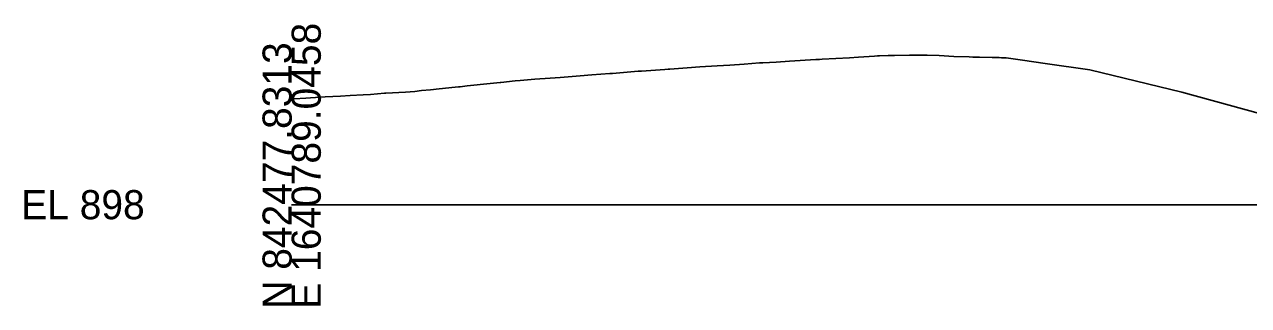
# Model space of a CAD drawing. Extents: x -26 to 1640245, y -10 to 842531.
# Drawn here: x -25.7 to 92, y 1990.3 to 2017.3 of the extents above; entities that cross this region are included whole.
import ezdxf

# ---------------------------------------------------------------- set-up
doc = ezdxf.new("R2010")
doc.units = 0
for name, color, linetype in [('Default', 7, 'Continuous'), ('Exist Cross Section Cell', 7, 'Continuous'), ('Exist XS Ground Line', 7, 'Continuous')]:
    doc.layers.add(name, color=color, linetype=linetype)

msp = doc.modelspace()

# ---------------------------------------------------------------- linework, layer by layer
at = {"layer": 'Exist Cross Section Cell'}
msp.add_line((0, 2000), (150, 2000), dxfattribs=at)
at = {"layer": 'Exist XS Ground Line'}
for p, q in [((50.76, 2013.96), (51.02, 2013.98)), ((51.02, 2013.98), (53.64, 2014.13)), ((53.64, 2014.13), (54.52, 2014.18)), ((54.52, 2014.18), (56.06, 2014.28)), ((56.06, 2014.28), (56.35, 2014.3)), ((56.35, 2014.3), (56.52, 2014.31)), ((56.52, 2014.31), (57.36, 2014.33)), ((57.36, 2014.33), (57.39, 2014.33)), ((57.39, 2014.33), (57.97, 2014.35)), ((57.97, 2014.35), (59.4, 2014.38)), ((59.4, 2014.38), (60.02, 2014.38)), ((60.02, 2014.38), (61.1, 2014.37)), ((61.1, 2014.37), (62.28, 2014.34)), ((62.28, 2014.34), (63.68, 2014.23)), ((63.68, 2014.23), (65.15, 2014.2)), ((65.15, 2014.2), (65.51, 2014.19)), ((65.51, 2014.19), (66.14, 2014.18)), ((66.14, 2014.18), (67.35, 2014.15)), ((67.35, 2014.15), (68.03, 2014.14)), ((68.03, 2014.14), (68.25, 2014.13)), ((68.25, 2014.13), (68.72, 2014.12)), ((68.72, 2014.12), (70.29, 2013.89)), ((30.85, 2012.62), (33.31, 2012.82)), ((33.31, 2012.82), (33.48, 2012.83)), ((33.48, 2012.83), (33.64, 2012.84)), ((33.64, 2012.84), (35.89, 2013)), ((35.89, 2013), (36.19, 2013.02)), ((36.19, 2013.02), (36.37, 2013.03)), ((36.37, 2013.03), (38.03, 2013.16)), ((38.03, 2013.16), (39.25, 2013.25)), ((39.25, 2013.25), (40.93, 2013.35)), ((40.93, 2013.35), (42.12, 2013.42)), ((42.12, 2013.42), (43.52, 2013.52)), ((43.52, 2013.52), (45, 2013.62)), ((45, 2013.62), (45.18, 2013.63)), ((45.18, 2013.63), (45.32, 2013.64)), ((45.32, 2013.64), (46.59, 2013.71)), ((46.59, 2013.71), (47.88, 2013.79)), ((47.88, 2013.79), (50.42, 2013.94)), ((50.42, 2013.94), (50.76, 2013.96)), ((70.29, 2013.89), (72.46, 2013.58)), ((72.46, 2013.58), (76.77, 2012.97)), ((76.77, 2012.97), (85.59, 2010.82)), ((16.87, 2011.41), (19.09, 2011.64)), ((19.09, 2011.64), (20.05, 2011.75)), ((20.05, 2011.75), (20.07, 2011.75)), ((20.07, 2011.75), (20.07, 2011.75)), ((20.07, 2011.75), (20.11, 2011.75)), ((20.11, 2011.75), (21.5, 2011.9)), ((21.5, 2011.9), (21.97, 2011.94)), ((21.97, 2011.94), (23.37, 2012.05)), ((23.37, 2012.05), (24.85, 2012.16)), ((24.85, 2012.16), (25.81, 2012.24)), ((25.81, 2012.24), (27.73, 2012.4)), ((27.73, 2012.4), (28.86, 2012.47)), ((28.86, 2012.47), (30.61, 2012.6)), ((30.61, 2012.6), (30.85, 2012.62)), ((4.7, 2010.44), (5.64, 2010.49)), ((5.64, 2010.49), (6.87, 2010.56)), ((6.87, 2010.56), (7.58, 2010.6)), ((7.58, 2010.6), (8.92, 2010.71)), ((8.92, 2010.71), (9.07, 2010.73)), ((9.07, 2010.73), (10.96, 2010.83)), ((10.96, 2010.83), (11.86, 2010.88)), ((11.86, 2010.88), (12.49, 2010.96)), ((12.49, 2010.96), (13.34, 2011.04)), ((13.34, 2011.04), (14.2, 2011.13)), ((14.2, 2011.13), (15.72, 2011.29)), ((15.72, 2011.29), (16.04, 2011.32)), ((16.04, 2011.32), (16.21, 2011.34)), ((16.21, 2011.34), (16.87, 2011.41)), ((85.59, 2010.82), (95.57, 2008.08)), ((0, 2010.17), (0.24, 2010.19)), ((0.24, 2010.19), (1.35, 2010.24)), ((1.35, 2010.24), (1.82, 2010.27)), ((1.82, 2010.27), (3.21, 2010.36)), ((3.21, 2010.36), (4.7, 2010.44))]:
    msp.add_line(p, q, dxfattribs=at)

# ---------------------------------------------------------------- texts
at = {"layer": 'Default'}
msp.add_text('-', height=0.0001, dxfattribs=at).set_placement((0, 2000))
at = {"layer": 'Exist Cross Section Cell'}
for s, p in [('E 1640789.0458', (2.8, 1990)), ('N 842477.8313', (0, 1990))]:
    msp.add_text(s, height=2.8, rotation=90, dxfattribs=at).set_placement(p)
msp.add_text('EL 898', height=2.8, dxfattribs=at).set_placement((-26, 1998.6))

doc.saveas('drawing.dxf')
